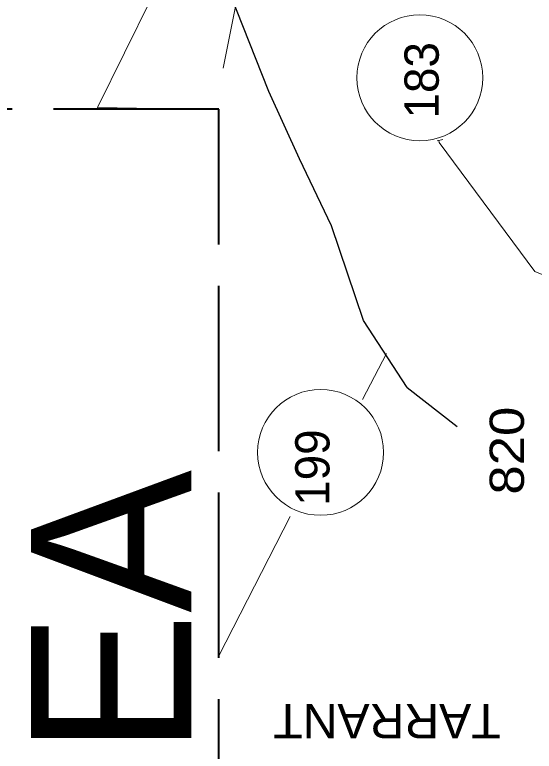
# Model space of a CAD drawing. Extents: x 2363323 to 2367082, y 6956018 to 6980837.
# Drawn here: x 2365930.2 to 2366007.5, y 6956720 to 6956829.6 of the extents above; entities that cross this region are included whole.
import ezdxf

# ---------------------------------------------------------------- set-up
doc = ezdxf.new("R2010")
doc.units = 0
doc.header["$LTSCALE"] = 4.1
doc.linetypes.add('LONG_DASHED', pattern=[7.5, 6, -1.5])
doc.layers.add('62', color=7, linetype='Continuous', lineweight=13)
doc.layers.add('63', color=7, linetype='Continuous', lineweight=13)

msp = doc.modelspace()

# ---------------------------------------------------------------- linework, layer by layer
at = {"layer": '62'}
for p, q in [((2365993.018, 6956810.859), (2365993.873, 6956811.084)), ((2365993.288, 6956810.902), (2365993.333, 6956810.632)), ((2365981.923, 6956772.357), (2365985.503, 6956779.244)), ((2365960.57, 6956734.26), (2365971.145, 6956754.963))]:
    msp.add_line(p, q, dxfattribs=at)
at = {"layer": '62', "lineweight": 25}
msp.add_line((2365988.585, 6956774.157), (2365995.989, 6956768.374), dxfattribs=at)
msp.add_lwpolyline([(2365988.585, 6956774.157), (2365982.059, 6956784.148), (2365977.31, 6956798.212), (2365972.563, 6956808.202), (2365967.974, 6956818.215), (2365963.204, 6956830.346), (2365960.39, 6956837.254), (2365960.391, 6956847.246), (2365960.391, 6956863.197), (2365961.447, 6956875.35), (2365964.261, 6956881.29), (2365967.231, 6956884.148)], dxfattribs=at)
at = {"layer": '62', "linetype": 'LONG_DASHED'}
for points in [[(2365942.522, 6956815.81), (2365972.045, 6956875.98), (2365959.964, 6956815.539)], [(2365942.522, 6956815.81), (2365972.045, 6956875.98), (2365959.964, 6956815.539), (2365942.522, 6956815.81)]]:
    msp.add_lwpolyline(points, close=True, dxfattribs=at)
at = {"layer": '62', "linetype": 'LONG_DASHED', "lineweight": 40}
msp.add_lwpolyline([(2365896.754, 6956641.712), (2365960.57, 6956641.71), (2365960.57, 6956815.562), (2365896.755, 6956815.562), (2365896.754, 6956641.395)], dxfattribs=at)
at = {"layer": '62'}
msp.add_lwpolyline([(2365993.333, 6956810.632), (2366007.575, 6956791.416), (2366024.836, 6956784.508)], dxfattribs=at)
for centre in [(2365990.454, 6956820.255), (2365975.698, 6956764.517)]:
    msp.add_circle(centre, 9.364, dxfattribs=at)
at = {"layer": '63'}
for p, q in [((2365993.018, 6956810.859), (2365993.873, 6956811.084)), ((2365993.288, 6956810.902), (2365993.333, 6956810.632)), ((2365981.923, 6956772.357), (2365985.503, 6956779.244)), ((2365960.57, 6956734.26), (2365971.145, 6956754.963))]:
    msp.add_line(p, q, dxfattribs=at)
at = {"layer": '63', "lineweight": 25}
msp.add_line((2365988.585, 6956774.157), (2365995.989, 6956768.374), dxfattribs=at)
msp.add_lwpolyline([(2365988.585, 6956774.157), (2365982.059, 6956784.148), (2365977.31, 6956798.212), (2365972.563, 6956808.202), (2365967.974, 6956818.215), (2365963.204, 6956830.346), (2365960.39, 6956837.254), (2365960.391, 6956847.246), (2365960.391, 6956863.197), (2365961.447, 6956875.35), (2365964.261, 6956881.29), (2365967.231, 6956884.148)], dxfattribs=at)
at = {"layer": '63', "linetype": 'LONG_DASHED'}
for points in [[(2365942.522, 6956815.81), (2365972.045, 6956875.98), (2365959.964, 6956815.539)], [(2365942.522, 6956815.81), (2365972.045, 6956875.98), (2365959.964, 6956815.539), (2365942.522, 6956815.81)]]:
    msp.add_lwpolyline(points, close=True, dxfattribs=at)
at = {"layer": '63', "linetype": 'LONG_DASHED', "lineweight": 40}
msp.add_lwpolyline([(2365896.754, 6956641.712), (2365960.57, 6956641.71), (2365960.57, 6956815.562), (2365896.755, 6956815.562), (2365896.754, 6956641.395)], dxfattribs=at)
at = {"layer": '63'}
msp.add_lwpolyline([(2365993.333, 6956810.632), (2366007.575, 6956791.416), (2366024.836, 6956784.508)], dxfattribs=at)
for centre in [(2365990.454, 6956820.255), (2365975.698, 6956764.517)]:
    msp.add_circle(centre, 9.364, dxfattribs=at)

# ---------------------------------------------------------------- texts
at = {"layer": '62'}
for s, height, p in [('183', 5.099, (2365993.264, 6956814.19)), ('199', 5.099, (2365977.016, 6956756.561)), ('AREA', 23.83, (2365956.474, 6956675.127))]:
    msp.add_text(s, height=height, rotation=90, dxfattribs=at).set_placement(p)
for s, rotation, width, p in [('820', 90, 1.15, (2366005.932, 6956758.227)), ('TARRANT', 180, 1.05, (2366002.467, 6956727.061))]:
    msp.add_text(s, height=5.099, rotation=rotation, dxfattribs=dict(at, width=width)).set_placement(p)
at = {"layer": '63'}
for s, height, p in [('183', 5.099, (2365993.264, 6956814.19)), ('199', 5.099, (2365977.016, 6956756.561)), ('AREA', 23.83, (2365956.474, 6956675.127))]:
    msp.add_text(s, height=height, rotation=90, dxfattribs=at).set_placement(p)
for s, rotation, width, p in [('820', 90, 1.15, (2366005.932, 6956758.227)), ('TARRANT', 180, 1.05, (2366002.467, 6956727.061))]:
    msp.add_text(s, height=5.099, rotation=rotation, dxfattribs=dict(at, width=width)).set_placement(p)

doc.saveas('drawing.dxf')
